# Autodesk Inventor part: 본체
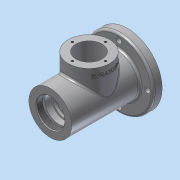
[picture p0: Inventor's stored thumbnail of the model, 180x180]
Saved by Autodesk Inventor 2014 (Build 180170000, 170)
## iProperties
Created: 2016-08
Part Number: 본체
Material: 알루미늄 6061
Document SubType Name: Modeling
Designer: 703-04
Density: 2.71 g/cm^3
Appearance: 알루미늄 - 평지
Author: 703-04
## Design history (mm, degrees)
sketch "스케치2"
  geometry: C1 r 31 at (0, 0); 1 further point
  constraints: 1 centre point, 1 coincident
  dimensions: "d0" = 62 diameter of C1
extrude "돌출1" new body sketch "스케치2" distance "d1" = 56; taper "d3" = 0 deg; dims "d2" = 59, "d4" = 0
node "작업 평면1"
sketch "스케치3"
  geometry: C1 r 50 at (0, 0); 1 further point
  constraints: 1 centre point, 1 coincident
  dimensions: "d6" = 100 diameter of C1
extrude "돌출2" join sketch "스케치3" distance "d7" = 13; taper "d8" = 0 deg
node "작업 평면2"
sketch "스케치4"
  geometry: C1 r 30 at (0, 0); 1 further point
  constraints: 1 centre point, 1 coincident
  dimensions: "d10" = 60 diameter of C1
extrude "돌출3" join sketch "스케치4" stored distance "d11" = 13; taper "d12" = 0 deg
node "작업 평면3"
sketch "스케치5"
  geometry: C1 r 26 at (0, -1.89); 1 further point
  constraints: 1 centre point
  dimensions: "d14" = 52 diameter of C1
extrude "돌출4" cut sketch "스케치5" stored distance "d15" = 38; taper "d16" = 0 deg
hole "구멍1" diameter "d19" = 40.376; stored, may be unused: countersink angle "d23" = 90 deg, drill point angle "d25" = 0 deg; dims "d17" = 10, "d18" = 10, "d20" = 6, "d21" = 4, "d22" = 2, "d24" = 9
node "작업 평면4"
node "작업 평면5"
sketch "스케치6"
  geometry: C1 r 24 at (0, 0); 1 further point
  constraints: 1 centre point, 1 coincident
  dimensions: "d27" = 48 diameter of C1
extrude "돌출5" cut sketch "스케치6" distance "d28" = 3; taper "d29" = 0 deg
hole "구멍2" diameter "d32" = 40; stored, may be unused: countersink angle "d36" = 90 deg, drill point angle "d38" = 0 deg; dims "d33" = 6, "d34" = 4, "d35" = 2, "d37" = 9, "d70" = 10, "d71" = 10
hole "구멍3" diameter "d41" = 35; stored, may be unused: countersink angle "d45" = 90 deg, drill point angle "d47" = 0 deg; dims "d39" = 10, "d40" = 10, "d42" = 6, "d43" = 4, "d44" = 2, "d46" = 3.25
hole "구멍4" diameter "d50" = 37; stored, may be unused: countersink angle "d54" = 90 deg, drill point angle "d56" = 0 deg; dims "d48" = 10, "d49" = 10, "d51" = 6, "d52" = 4, "d53" = 2, "d55" = 1.75
sketch "스케치7"
  geometry: L1 (-31, -59)-(31, -59) reference; L2 (21, -59)-(16, -45); L3 (0, -70.8)-(0, 11.8) reference; L4 (16, -45)-(12.5, -45); L5 (12.5, -45)-(12.5, -37.7); L6 (12.5, -37.7)-(10, -37.7); L7 (10, -37.7)-(10, -35); L8 (10, -35)-(0, -35); L9 (21, -59)-(0, -59); L10 (0, -59)-(0, -35); 1 further point
  constraints: 16 end point, 3 perpendicular, 3 point on line, 2 parallel, 1 collinear, 1 midpoint
  dimensions: "d57" = 42 diameter of L2.start L3; "d58" = 32 diameter of L2.end L3; "d59" = 14 vertical distance of L2.start L2.end; "d60" = 25 diameter of L5 L3; "d61" = 7.3 distance of L4.end L5.end; "d62" = 20 diameter of L7 L3; "d63" = 2.7 distance of L6.end L7.end
revolve "회전1" sketch "스케치7" stored, may be unused: angle "d64" = 90 deg
sketch "스케치8"
  geometry: C1 r 17.5 at (0, 0); 1 further point
  constraints: 1 centre point, 1 coincident
  dimensions: "d65" = 35 diameter of C1
extrude "돌출6" cut sketch "스케치8" stored distance "d66" = 60; taper "d67" = 0 deg
hole "구멍5" diameter "d72" = 33; stored, may be unused: countersink angle "d76" = 90 deg, drill point angle "d78" = 0 deg; dims "d68" = 10, "d69" = 10, "d73" = 6, "d74" = 4, "d75" = 2, "d77" = 5
fillet "모깎기1" dims "d79" = 3
fillet "모깎기2" dims "d80" = 0.3
chamfer "모따기2" distance "d84" = 0.7; stored, may be unused: second distance "d85" = 2, angle "d86" = 60 deg
hole "구멍6" diameter "d89" = 38; stored, may be unused: countersink angle "d93" = 90 deg, drill point angle "d95" = 0 deg; dims "d87" = 10, "d88" = 10, "d90" = 6, "d91" = 4, "d92" = 2, "d94" = 50
sketch "스케치9"
  geometry: C1 r 19 at (0, 0) reference; 1 further point
  constraints: 1 vertical alignment
  dimensions: "d96" = 24 distance of point (0, 24) C1.centre
hole "구멍7" sketch "스케치9" at (0, 24) diameter "d97" = 3.242; stored, may be unused: countersink angle "d101" = 90 deg, drill point angle "d103" = 118 deg; dims "d98" = 8, "d99" = 4, "d100" = 2, "d102" = 10
chamfer "모따기3" distance "d107" = 1; stored, may be unused: second distance "d108" = 2, angle "d109" = 60 deg
fillet "모깎기3" dims "d110" = 3
sketch "스케치10"
  geometry: C1 r 50 at (0, 0) reference; 1 further point
  constraints: 1 vertical alignment
  dimensions: "d111" = 41.5 distance of point (0, 41.5) C1.centre
hole "구멍8" sketch "스케치10" at (0, 41.5) diameter "d112" = 8; stored, may be unused: countersink angle "d116" = 90 deg, drill point angle "d118" = 0 deg; dims "d113" = 8, "d114" = 4, "d115" = 2, "d117" = 20
node "작업 평면6"
sketch "스케치11"
  geometry: L1 (31, 56)-(-31, 56) reference; L2 (49, 30)-(49, -30) reference; 2 further points
  constraints: 1 other
  dimensions: "d123" = 56 distance from line of point (39, 0) L1; "d124" = 10 distance from line of point (39, 0) L2
feature "엠보싱1" sketch "스케치11" dims "d125" = 0.5, "d126" = 0
node "솔리드1"
pattern_circular "원형 패턴1" dims angle "d105" = 360 deg
pattern_circular "원형 패턴2" dims angle "d120" = 360 deg
other parameters: "d5" = -3, "d9" = 49, "d13" = -56, "d26" = -9
